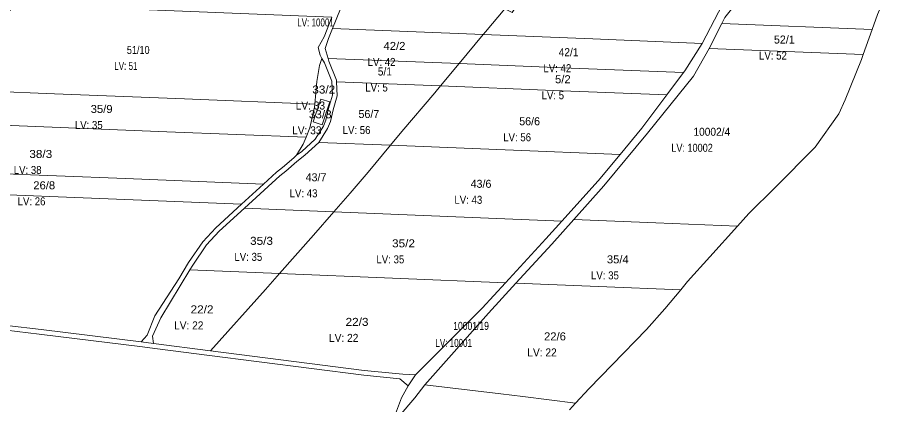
# Model space of a CAD drawing. Extents: x -713758 to -711119, y -1123067 to -1120789.
# Drawn here: x -712228 to -711119, y -1122197 to -1121714 of the extents above; entities that cross this region are included whole.
import ezdxf
from ezdxf.enums import TextEntityAlignment as Align

# ---------------------------------------------------------------- set-up
doc = ezdxf.new("R2010")
doc.units = 0
doc.header["$LTSCALE"] = 4
doc.layers.add('10', color=7, linetype='Continuous', lineweight=13)
doc.layers.add('11', color=7, linetype='Continuous')
doc.layers.add('13', color=7, linetype='Continuous')

msp = doc.modelspace()

# ---------------------------------------------------------------- linework, layer by layer
at = {"layer": '10'}
for points in [[(-711348.65, -1121721.62), (-711344.84, -1121714.14), (-711327.93, -1121693.04), (-711309.78, -1121645.54), (-711280.48, -1121583.19), (-711274.65, -1121570.23), (-711152.83, -1121575.14), (-711143.77, -1121586.94), (-711134.29, -1121605.95), (-711127.43, -1121622.47), (-711119.27, -1121636.2), (-711137.38, -1121671.56), (-711153.77, -1121710.26), (-711160.57, -1121729.14)], [(-711835.08, -1121727.68), (-711815.31, -1121678.11), (-711786.19, -1121602.57), (-711783.2, -1121595.79), (-711668.6, -1121600.39), (-711553.99, -1121604.99), (-711562.27, -1121620.75), (-711593.45, -1121681.64), (-711656.45, -1121644), (-711672.97, -1121675.46), (-711663.14, -1121682.15), (-711619.93, -1121703.21), (-711643.78, -1121731.83), (-711646.68, -1121735.31)], [(-711646.68, -1121735.31), (-711643.78, -1121731.83), (-711619.93, -1121703.21), (-711610.76, -1121707.68), (-711593.45, -1121681.64), (-711562.27, -1121620.75), (-711553.99, -1121604.99), (-711431.22, -1121609.91), (-711308.45, -1121614.84), (-711315.94, -1121630.99), (-711342.08, -1121687.09), (-711372.92, -1121746.38), (-711509.8, -1121740.84)], [(-712345.4, -1121802.72), (-712182.69, -1121809.23), (-712019.97, -1121815.74), (-711857.26, -1121822.25), (-711854.58, -1121793.79), (-711851.16, -1121773.83), (-711848.33, -1121765.03), (-711850.53, -1121760.95), (-711852.87, -1121751.59), (-711845.69, -1121738.11), (-711835.92, -1121713.6), (-712032.9, -1121705.73), (-712229.88, -1121697.85)], [(-711844.39, -1121752.75), (-711840.69, -1121765.13), (-711677, -1121771.68), (-711646.68, -1121735.31), (-711835.08, -1121727.68), (-711840.12, -1121740.33)], [(-711364.41, -1121752.56), (-711171.77, -1121760.26), (-711160.57, -1121729.14), (-711348.65, -1121721.62)], [(-711677, -1121771.68), (-711646.68, -1121735.31), (-711509.8, -1121740.84), (-711372.92, -1121746.38), (-711394.73, -1121780.84), (-711396.29, -1121782.9), (-711536.65, -1121777.29)], [(-711533.39, -1121966.28), (-711495.79, -1121924.47), (-711441.43, -1121858.3), (-711384.1, -1121787.5), (-711364.41, -1121752.56), (-711171.77, -1121760.26), (-711173.98, -1121766.39), (-711194.24, -1121816.94), (-711202.13, -1121834.49), (-711232.04, -1121875.98), (-711281.99, -1121926.18), (-711314.68, -1121958.84), (-711329.01, -1121974.63), (-711431.2, -1121970.46)], [(-711879.9, -1121886.06), (-711873.61, -1121881.61), (-711856.81, -1121866.09), (-711846.53, -1121849.86), (-711843.27, -1121842.15), (-711840.08, -1121827.8), (-711835.27, -1121811.16), (-711836.05, -1121793.75), (-711845.28, -1121770.72), (-711848.33, -1121765.03), (-711851.16, -1121773.83), (-711854.58, -1121793.79), (-711857.26, -1121822.25), (-711857.61, -1121825.96), (-711863.56, -1121851.73), (-711868.22, -1121863.68), (-711871.58, -1121872.29)], [(-711840.69, -1121765.13), (-711677, -1121771.68), (-711700.18, -1121799.47), (-711830.02, -1121794.28), (-711830.1, -1121792.46), (-711839.61, -1121768.74)], [(-711700.18, -1121799.47), (-711677, -1121771.68), (-711536.65, -1121777.29), (-711396.29, -1121782.9), (-711417.41, -1121810.78), (-711558.79, -1121805.13)], [(-711852.16, -1121869.96), (-711841.19, -1121852.65), (-711837.53, -1121843.99), (-711834.27, -1121829.3), (-711829.23, -1121811.88), (-711830.02, -1121794.28), (-711700.18, -1121799.47), (-711707.32, -1121808.04), (-711748.51, -1121856.49), (-711762.67, -1121873.53)], [(-712390.45, -1121842.79), (-712216.37, -1121849.75), (-712042.3, -1121856.72), (-711868.22, -1121863.68), (-711863.56, -1121851.73), (-711857.61, -1121825.96), (-711857.26, -1121822.25), (-712019.97, -1121815.74), (-712182.69, -1121809.23), (-712345.4, -1121802.72), (-712370.34, -1121801.72), (-712370.07, -1121815.62), (-712372.12, -1121824.42), (-712375.18, -1121829.75), (-712381, -1121835.02)], [(-711762.67, -1121873.53), (-711748.51, -1121856.49), (-711707.32, -1121808.04), (-711700.18, -1121799.47), (-711558.79, -1121805.13), (-711417.41, -1121810.78), (-711448.7, -1121852.1), (-711475.78, -1121884.98), (-711619.22, -1121879.26)], [(-711859.12, -1121844.26), (-711849.68, -1121815.97), (-711838.29, -1121819.55), (-711847.98, -1121848.23)], [(-711859.12, -1121844.26), (-711847.98, -1121848.23), (-711838.29, -1121819.55), (-711849.68, -1121815.97)], [(-712439.32, -1121901.5), (-712266.67, -1121908.4), (-712094.01, -1121915.31), (-711921.36, -1121922.21), (-711905.03, -1121907.27), (-711897.42, -1121901.24), (-711883.6, -1121889.47), (-711879.9, -1121886.06), (-711871.58, -1121872.29), (-711868.22, -1121863.68), (-712042.3, -1121856.72), (-712216.37, -1121849.75), (-712390.45, -1121842.79), (-712418.13, -1121861.03), (-712427.59, -1121870.3)], [(-711945.29, -1121952.23), (-711901.13, -1121911.84), (-711893.61, -1121905.88), (-711879.62, -1121893.96), (-711869.54, -1121886.02), (-711852.16, -1121869.96), (-711762.67, -1121873.53), (-711790.68, -1121907.26), (-711812.86, -1121933.67), (-711833.26, -1121956.77)], [(-711833.26, -1121956.77), (-711812.86, -1121933.67), (-711790.68, -1121907.26), (-711762.67, -1121873.53), (-711619.22, -1121879.26), (-711475.78, -1121884.98), (-711503, -1121918.04), (-711548.35, -1121968.31), (-711690.8, -1121962.54)], [(-712449, -1121927.24), (-712282.24, -1121933.91), (-712115.49, -1121940.58), (-711948.74, -1121947.25), (-711921.36, -1121922.21), (-712094.01, -1121915.31), (-712266.67, -1121908.4), (-712439.32, -1121901.5)], [(-712013.51, -1122029.33), (-712009.85, -1122023.27), (-711992.41, -1121997.99), (-711976.73, -1121980.98), (-711945.29, -1121952.23), (-711833.26, -1121956.77), (-711859.05, -1121985.97), (-711901.28, -1122033.88)], [(-711901.28, -1122033.88), (-711859.05, -1121985.97), (-711833.26, -1121956.77), (-711690.8, -1121962.54), (-711548.35, -1121968.31), (-711568.44, -1121990.58), (-711618.99, -1122045.32), (-711760.14, -1122039.6)], [(-711605.83, -1122045.85), (-711561.18, -1121997.19), (-711533.39, -1121966.28), (-711431.2, -1121970.46), (-711329.01, -1121974.63), (-711363.69, -1122012.86), (-711391.24, -1122043.97), (-711399.78, -1122054.2), (-711502.8, -1122050.02)], [(-712060.12, -1122111.92), (-712049.64, -1122089.23), (-712013.51, -1122029.33), (-711901.28, -1122033.88), (-711918.95, -1122053.93), (-711987.5, -1122130.41), (-712058.65, -1122121.31)], [(-711987.5, -1122130.41), (-711918.95, -1122053.93), (-711901.28, -1122033.88), (-711760.14, -1122039.6), (-711618.99, -1122045.32), (-711648.26, -1122077.01), (-711731.33, -1122160.31), (-711747.24, -1122159.69), (-711795.47, -1122154.99)], [(-711719.68, -1122173.09), (-711640.25, -1122083.36), (-711605.83, -1122045.85), (-711502.8, -1122050.02), (-711399.78, -1122054.2), (-711419.64, -1122078), (-711442.51, -1122103.83), (-711485.77, -1122147.81), (-711514.13, -1122177.55), (-711531.33, -1122195.96), (-711597.08, -1122187.53), (-711624.53, -1122184.01)]]:
    msp.add_lwpolyline(points, close=True, dxfattribs=at)
for points in [[(-711835.92, -1121713.6), (-711845.69, -1121738.11), (-711852.87, -1121751.59), (-711850.53, -1121760.95), (-711848.33, -1121765.03), (-711845.28, -1121770.72), (-711836.05, -1121793.75), (-711835.27, -1121811.16), (-711840.08, -1121827.8), (-711843.27, -1121842.15), (-711846.53, -1121849.86), (-711856.81, -1121866.09), (-711873.61, -1121881.61), (-711879.9, -1121886.06), (-711883.6, -1121889.47), (-711897.42, -1121901.24), (-711905.03, -1121907.27), (-711921.36, -1121922.21), (-711948.74, -1121947.25), (-711980.97, -1121976.73), (-711997.11, -1121994.23), (-712014.89, -1122020.02), (-712027.14, -1122040.31), (-712056.97, -1122086.71), (-712066.67, -1122110.74), (-712074.33, -1122119.19), (-712058.65, -1122121.31), (-712060.12, -1122111.92), (-712049.64, -1122089.23), (-712013.51, -1122029.33), (-712009.85, -1122023.27), (-711992.41, -1121997.99), (-711976.73, -1121980.98), (-711945.29, -1121952.23), (-711901.13, -1121911.84), (-711893.61, -1121905.88), (-711879.62, -1121893.96), (-711869.54, -1121886.02), (-711852.16, -1121869.96), (-711841.19, -1121852.65), (-711837.53, -1121843.99), (-711834.27, -1121829.3), (-711829.23, -1121811.88), (-711830.02, -1121794.28), (-711830.1, -1121792.46), (-711839.61, -1121768.74), (-711840.69, -1121765.13), (-711844.39, -1121752.75), (-711840.12, -1121740.33), (-711835.08, -1121727.68), (-711815.31, -1121678.11)], [(-711342.08, -1121687.09), (-711372.92, -1121746.38), (-711394.73, -1121780.84), (-711396.29, -1121782.9), (-711417.41, -1121810.78), (-711448.7, -1121852.1), (-711475.78, -1121884.98), (-711503, -1121918.04), (-711548.35, -1121968.31), (-711568.44, -1121990.58), (-711618.99, -1122045.32), (-711648.26, -1122077.01), (-711731.33, -1122160.31), (-711740.44, -1122174.1), (-711748.73, -1122189.21), (-711756.25, -1122209.29)], [(-711751.85, -1122212.21), (-711732.41, -1122188.95), (-711719.68, -1122173.09), (-711640.25, -1122083.36), (-711605.83, -1122045.85), (-711561.18, -1121997.19), (-711533.39, -1121966.28), (-711495.79, -1121924.47), (-711441.43, -1121858.3), (-711384.1, -1121787.5), (-711364.41, -1121752.56), (-711348.65, -1121721.62), (-711344.84, -1121714.14)], [(-712282.24, -1121933.91), (-712115.49, -1121940.58), (-711948.74, -1121947.25), (-711980.97, -1121976.73), (-711997.11, -1121994.23), (-712014.89, -1122020.02), (-712027.14, -1122040.31), (-712056.97, -1122086.71), (-712066.67, -1122110.74), (-712074.33, -1122119.19), (-712199.3, -1122103.98), (-712242.32, -1122098.75)], [(-712593.46, -1122311.4), (-712570.37, -1122127.1), (-712555.16, -1122125.19), (-712537.6, -1122122.97), (-712471.79, -1122114.69), (-712453.08, -1122113.47), (-712414.27, -1122110.94), (-712412.73, -1122110.84), (-712274.36, -1122101.82), (-712242.94, -1122104.72), (-712201.72, -1122109.73), (-712072.6, -1122125.44), (-712066.77, -1122126.32), (-711992.36, -1122135.84), (-711796.12, -1122160.95), (-711751.06, -1122165.34), (-711740.44, -1122174.1), (-711748.73, -1122189.21), (-711756.25, -1122209.29)], [(-712242.94, -1122104.72), (-712201.72, -1122109.73), (-712072.6, -1122125.44), (-712066.77, -1122126.32), (-711992.36, -1122135.84), (-711796.12, -1122160.95), (-711751.06, -1122165.34), (-711740.44, -1122174.1), (-711731.33, -1122160.31), (-711747.24, -1122159.69), (-711795.47, -1122154.99), (-711987.5, -1122130.41), (-712058.65, -1122121.31), (-712074.33, -1122119.19), (-712199.3, -1122103.98), (-712242.32, -1122098.75)], [(-711538.98, -1122204.15), (-711531.33, -1122195.96), (-711597.08, -1122187.53), (-711624.53, -1122184.01), (-711719.68, -1122173.09), (-711732.41, -1122188.95), (-711751.85, -1122212.21)]]:
    msp.add_lwpolyline(points, dxfattribs=at)

# ---------------------------------------------------------------- texts
at = {"layer": '11'}
for s, p in [('52/1', (-711270.38, -1121746.55)), ('56/7', (-711789.64, -1121839.58)), ('56/6', (-711588.75, -1121848.64)), ('43/7', (-711855.71, -1121918.64)), ('43/6', (-711649.51, -1121926.77))]:
    msp.add_text(s, height=10, dxfattribs=at).set_placement(p, align=Align.CENTER)
for s, width, p in [('51/10', 0.85, (-712077.931, -1121759.54)), ('42/2', 1.05, (-711757.671, -1121754.53)), ('42/1', 0.95, (-711540.06, -1121762.35)), ('5/1', 0.95, (-711769.64, -1121786.46)), ('5/2', 1.05, (-711547.2, -1121796.14)), ('33/2', 1.1, (-711846.041, -1121809)), ('35/9', 1.05, (-712123.689, -1121833.27)), ('33/3', 1.1, (-711850.429, -1121839.93)), ('10002/4', 0.95, (-711361.061, -1121861.77)), ('38/3', 1.1, (-712199.74, -1121889.48)), ('26/8', 1.05, (-712195.43, -1121928.65)), ('35/3', 1.1, (-711923.81, -1121998.02)), ('35/2', 1.1, (-711746.36, -1122001.14)), ('35/4', 1.05, (-711478.53, -1122021.14)), ('22/2', 1.1, (-711998.17, -1122083.64)), ('22/3', 1.1, (-711804.47, -1122099.26)), ('10001/19', 0.8, (-711661.9, -1122104.25)), ('22/6', 1.05, (-711557.041, -1122117.39))]:
    msp.add_text(s, height=10, dxfattribs=dict(at, width=width)).set_placement(p, align=Align.CENTER)
at = {"layer": '13'}
for s, width, p in [('LV: 10001 ', 0.75, (-711854.924, -1121725.21)), ('LV: 52 ', 0.9, (-711282.961, -1121766.55)), ('LV: 51 ', 0.75, (-712091.984, -1121779.54)), ('LV: 42 ', 0.9, (-711772.126, -1121774.53)), ('LV: 42 ', 0.9, (-711552.407, -1121782.35)), ('LV: 5 ', 0.9, (-711778.407, -1121806.46)), ('LV: 5 ', 0.9, (-711558.075, -1121816.14)), ('LV: 33 ', 0.95, (-711860.998, -1121829)), ('LV: 35 ', 0.9, (-712138.078, -1121853.27)), ('LV: 33 ', 0.95, (-711865.454, -1121859.93)), ('LV: 56 ', 0.9, (-711803.392, -1121859.58)), ('LV: 56 ', 0.9, (-711602.703, -1121868.64)), ('LV: 10002 ', 0.85, (-711384.148, -1121881.77)), ('LV: 38 ', 0.9, (-712214.463, -1121909.48)), ('LV: 43 ', 0.9, (-711869.663, -1121938.64)), ('LV: 26 ', 0.9, (-712209.618, -1121948.65)), ('LV: 43 ', 0.9, (-711663.664, -1121946.77)), ('LV: 35 ', 0.9, (-711938.633, -1122018.02)), ('LV: 35 ', 0.9, (-711761.117, -1122021.14)), ('LV: 35 ', 0.9, (-711492.917, -1122041.14)), ('LV: 22 ', 0.95, (-712012.993, -1122103.64)), ('LV: 22 ', 0.95, (-711819.36, -1122119.26)), ('LV: 10001 ', 0.75, (-711682.236, -1122125.52)), ('LV: 22 ', 0.95, (-711571.495, -1122137.39))]:
    msp.add_text(s, height=10, dxfattribs=dict(at, width=width)).set_placement(p, align=Align.CENTER)

doc.saveas('drawing.dxf')
